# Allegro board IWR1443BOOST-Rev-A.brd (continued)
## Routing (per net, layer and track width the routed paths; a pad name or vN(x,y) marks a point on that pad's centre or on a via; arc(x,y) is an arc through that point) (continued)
AR_SPICLK1: length 44.7
  TOP w0.102: v1(37.19,33.76) 36.37,34.58 36.37,35.19 36.18,35.38 R76.1 35.04,35.38 R75.1 ; v1(60.55,53.34) 60.5,53.29 60.5,49.99 60.5,49.99 60.5,46.82 60.24,46.56 60.24,46.45 U2.R9
  L4 w0.127: v1(60.55,53.34) 56.84,53.34 55.62,52.12 54.62,52.12 49.24,46.75 47.42,46.75 41.83,41.16 40.33,41.16 36.87,37.71 36.87,34.07 v1(37.19,33.76)
AR_SYNC_IN: length 87.2
  TOP w0.102: v1(27.27,46.79) 27.27,46.3 26.64,45.67 26.64,44.91 26.47,44.74 R62.2 ; U2.N10 59.59,44.87 59.91,44.55 59.91,43.81 v1(60.2,43.53)
  L3 w0.127: v1(27.27,46.79) 28.32,47.83 29.44,47.83 29.85,47.42 34.77,47.42 37.36,44.83 46.8,44.83 48.12,46.15 54.22,46.15 54.96,45.42 59.21,45.42 59.89,44.74 59.89,43.84 v1(60.2,43.53)
  L4 w0.127: v1(25.67,21.51) 23.34,19.18 v1(23.34,15.82)
  BOTTOM w0.102: R165.1 26,8.11 25.9,8.21 25.9,9.09 25.06,9.93 25.06,14.07 23.34,15.8 v1(23.34,15.82) ; v1(27.27,46.79) 27.85,46.79 32.24,42.39 32.24,35.58 32.07,35.41 32.07,27.91 v1(25.67,21.51)
AR_SYNC_OUT_SOP1: length 95
  TOP w0.102: v1(57.91,51.18) 59.48,49.61 59.48,47.5 58.62,46.65 58.62,45.88 U2.P11 ; R113.1 18.61,14.48 29.44,14.48 29.64,14.29 31.03,14.29 31.21,14.46 33.26,14.46 35.94,17.13 R108.2 36.4,19.89 v1(36.23,20.07)
  L3 w0.127: v1(38.73,53.26) 38.73,53.35 39.63,54.25 40.13,54.25 40.58,54.71 42.07,54.71 43.01,53.77 43.89,53.77 43.98,53.86 46.27,53.86 49.32,56.91 51.56,56.91 54.75,53.71 54.75,52.77 55.13,52.39 55.64,52.39 56.69,51.35 57.74,51.35 v1(57.91,51.18)
  BOTTOM w0.102: v1(38.73,53.26) 35.06,53.26 31.78,49.98 31.78,45.08 33.93,42.93 33.93,33.76 33.32,33.15 33.32,32.13 33.88,31.57 33.88,25.17 33.38,24.67 33.38,22.85 36.16,20.07 v1(36.23,20.07)
AR_TCK: length 33.2
  TOP w0.102: R70.1 30.34,43.88 R66.2 30.57,44.74 30.7,44.86 30.7,45.87 v1(30.22,46.35) ; U2.M13 57.65,44.25 v1(58.13,44.25)
  L3 w0.127: v1(30.22,46.35) 31.03,47.17 34.67,47.17 37.26,44.58 46.91,44.58 47.13,44.81 50.87,44.81 51.56,44.12 56,44.12 56.13,44.25 v1(58.13,44.25)
AR_TDI: length 51.2
  TOP w0.102: U2.H13 58.05,41.67 v1(58.13,41.59) ; R29.1 R30.1 27.9,59.07 27.8,59.17 27.77,59.17 27.77,59.21 v1(27.76,59.21)
  L3 w0.127: v1(26.05,46.15) 26.05,45.43 27.87,43.61 35.66,43.61 38.4,40.87 51.5,40.87 52.24,41.61 56.86,41.61 56.88,41.59 v1(58.13,41.59)
  BOTTOM w0.102: v1(26.05,46.15) 25.83,46.38 25.83,50.57 26.83,51.58 26.83,56.7 26.57,56.96 26.57,58.02 v1(27.76,59.21)
AR_TDO_SOP0: length 56.6
  TOP w0.102: R89.1 27.55,24.96 v1(27.58,24.99) ; v1(59.01,42.37) 58.96,42.32 U2.J13 ; v1(30.3,42.37) 30.98,42.37 31.53,42.92 31.53,43.65 31.31,43.87 R71.1 31.17,43.87 R67.2 31.55,44.74 32.45,45.64 v1(32.45,46.28)
  L3 w0.127: v1(32.45,46.28) 33.42,46.28 38.58,41.12 51.12,41.12 52.26,42.26 58.9,42.26 v1(59.01,42.37)
  BOTTOM w0.102: v1(27.58,24.99) 30.28,27.7 30.28,33.84 29.58,34.54 29.58,41.66 v1(30.3,42.37)
AR_TMS: length 38.8
  TOP w0.102: v1(28.11,44.27) 28.19,44.27 28.59,43.87 R69.1 R65.2 ; U2.L13 58.82,43.62 v1(58.9,43.54)
  L3 w0.127: v1(28.11,44.27) 29.55,44.27 32.19,46.92 33.27,46.92 38.81,41.38 50.84,41.38 52.2,42.74 56.97,42.74 57.78,43.54 v1(58.9,43.54)
AR_VBGAP: length 2.3
  TOP w0.381: U2.B10 59.59,37.84 v1(59.13,38.3)
  BOTTOM w0.508: v1(59.13,38.3) 58.32,37.49 C56.2
AR_VOUT_PA:
  vias: v1(66.72,33.74) v1(66.82,34.53)
AR_VSENSE: length 62.2
  TOP w0.102: v1(56.99,39.07) U2.C14
  L3 w0.127: P1.1 5.33,47.29 5.33,42.71 7.98,40.06 51.68,40.06 52.7,41.07 55.46,41.07 56.52,40.01 56.52,39.54 v1(56.99,39.07)
AR_WARMRST: length 40.6
  TOP w0.102: v1(55.24,49.12) 55.14,49.12 55.04,49.02 55.04,48.01 56.66,46.38 56.66,46.1 56.87,45.88 57.12,45.88 57.32,45.69 57.32,45.44 57.52,45.24 57.97,45.24 U2.N12 ; R18.1 28.73,58.6 29.67,59.54 30.65,59.54 30.91,59.28 R15.1 31.14,58.67 31.18,58.67 31.21,58.65 31.21,58.6 31.69,58.12 v1(31.69,58.01)
  L3 w0.127: v1(55.24,49.12) 54.48,49.89 54.48,51.58 52.85,53.2 47.39,53.2 46.32,52.13 43.53,52.13 42.56,53.1 41.24,53.1 41.04,52.9 39.26,52.9 38.99,52.63 38.45,52.63 38.09,52.98 35.52,52.98 32.73,55.77 32.73,56.97 v1(31.69,58.01)
AR_XTALM: length 7.8
  TOP w0.102: C9.2 51.42,38.27 Y1.1 51.94,37.98 52.83,38.86 54.91,38.86 56.19,40.15 56.77,40.15 U2.F14
AR_XTALP: length 7.4
  TOP w0.102: U2.E14 56.83,39.72 56.5,39.39 56.09,39.39 55.11,38.4 55.11,37.08 53.79,35.77 Y1.3 54.06,35.33 C15.2
CAN1_RX: length 39.4
  TOP w0.102: v1(31.79,36.22) 29.94,36.22 28.44,34.72 28.44,32.74 29.08,32.11 U3.4 ; R12.2 25.27,62 v1(25.15,62.12)
  BOTTOM w0.102: v1(31.79,36.22) 31.79,42.51 28.26,46.04 27.29,46.04 26.95,45.7 25.77,45.7 24.68,46.79 24.68,55.93 24.28,56.33 24.28,59.29 25.15,60.16 v1(25.15,62.12)
CAN1_TX: length 37.4
  TOP w0.102: R11.2 30.33,61.94 30.3,61.98 v1(30.3,62.1) ; v1(32.61,30.35) 32.89,30.63 U3.1
  BOTTOM w0.102: v1(32.61,30.35) 32.35,30.61 32.35,33.6 33.01,34.26 33.01,42.49 28.17,47.33 28.17,52.13 30.33,54.28 30.33,58.66 30.57,58.9 30.57,59.31 30.3,59.58 v1(30.3,62.1)
LDO_01_EN: length 2.7
  TOP w0.305: U4.5 52.06,25.77
  TOP w0.508: R83.1 R84.2 52.06,25.77
LDO_02_EN: length 9.7
  TOP w0.102: R46.2 40.36,46.26 R47.1 42.38,46.26 v1(42.49,46.15)
  L3 w0.127: v1(42.49,46.15) 42.49,50.43 v1(42.97,50.91)
  BOTTOM w0.102: v1(42.97,50.91) 43.02,50.91 43.64,50.3 U5.6 ; v1(42.49,46.15) 42.71,45.93 U5.20
MCU_3V3: length 78.3
  TOP w0.889: v1(20.72,13.84) 21.05,13.51 31.48,13.51 31.81,13.84 33.8,13.84 v1(34.94,14.99) ; v1(41.57,53.82) 40.3,52.55 39.21,52.55 37.1,50.44 37.1,47.76 38.98,45.89 v1(38.98,45.72)
  L4 w0.889: v1(34.94,14.99) 34.94,14.99 35.1,15.14 35.1,21.87 35.48,22.25 35.48,30.26 35.25,30.49 35.25,33.2 34.64,33.81 34.64,41.39 v1(38.98,45.72)
  BOTTOM w0.889: v1(41.57,53.82) 41.57,55.75 42.46,56.64 43.22,56.64 47.34,60.76 J4.3 ; R130.1 v1(38.98,45.72)
  BOTTOM w1.016: J6.1 16.01,13.12 16.73,13.84 v1(20.72,13.84)
MCU_5V: length 2.9
  BOTTOM w1.016: v1(15.08,18.53) 15.08,18.48 16.01,17.55 J6.2 16.7,16.66 v1(17.04,16.66)
  vias: v1(13.84,18.5) v1(16.94,18.58) v1(47.95,14.61) v1(48.05,15.54) v1(48.2,13.72) v1(49.4,13.67)
MCU_SOP0: length 42.7
  TOP w0.102: v1(37.87,53.8) 38.07,54.01 R36.1 ; R93.2 27.54,20.96 28.82,20.96 v1(29.08,21.21)
  BOTTOM w0.102: v1(29.08,21.21) 33.6,25.73 33.6,31.45 33.07,31.97 33.07,33.23 33.69,33.85 33.69,42.83 31.55,44.98 31.55,50.08 35.01,53.54 37.61,53.54 v1(37.87,53.8)
MCU_SOP1: length 51.4
  TOP w0.102: R112.2 19.56,15.02 19.68,15.14 19.68,16.59 21.98,18.9 25.47,18.9 v1(26.61,20.04) ; v1(35.4,54) 35.43,54 35.43,54.01 R35.1
  BOTTOM w0.102: v1(26.61,20.04) 26.61,21.26 33.32,27.97 33.32,31.32 32.84,31.79 32.84,33.33 33.46,33.95 33.46,42.73 31.32,44.87 31.32,50.38 34.94,54 v1(35.4,54)
MCU_SOP2: length 64.6
  TOP w0.102: v1(25.65,20.29) 25.51,20.16 21.09,20.16 18.85,22.4 11.96,22.4 11.6,22.05 11.6,17.86 R101.2 ; R32.1 v1(34.26,58.55)
  BOTTOM w0.102: v1(25.65,20.29) 25.65,20.68 33.09,28.12 33.09,31.14 32.61,31.62 32.61,33.43 33.23,34.05 33.23,42.6 31.09,44.75 31.09,50.66 32.94,52.5 32.94,57.23 v1(34.26,58.55)
PGOOD: length 115.6
  TOP w0.381: R27.1 24.62,58.91 24.25,59.28
  TOP w0.508: 24.25,59.28 23.54,59.28 v1(23.21,58.95) ; R107.2 32.07,17.29 32.13,17.23 v1(32.2,17.23) 32.28,17.23 32.79,17.74 32.79,18.88 35.35,21.45 35.35,28.35 37.33,30.34 37.33,32.59 v1(36.19,33.73)
  L3 w0.508: v1(23.21,58.95) 26.27,58.95 28.54,61.23 37.69,61.23 38.35,61.89 43.1,61.89 45.26,59.73 v1(45.26,57.35) ; v1(2.03,18.97) 4.2,18.97 4.47,18.71 10.45,18.71 11.56,19.82 19.42,19.82 20.21,19.04 24.87,19.04 25.92,18 31.36,18 32.13,17.23 v1(32.2,17.23)
  L4 w0.508: v1(45.26,57.35) 46.85,55.76 46.85,52.02 48.47,50.39 48.47,48.44 41.65,41.62 39.57,41.62 35.5,37.55 35.5,34.42 v1(36.19,33.73)
  BOTTOM w0.508: R159.1 2.37,18.63 v1(2.03,18.97) ; v1(36.19,33.73) 35.89,34.03 R138.2 35.97,34.46 R141.2
PMIC_1V2: length 26.1
  TOP w0.254: U2.P14 U2.P15 55.88,45.57 55.21,46.23 ; 56.15,47.47 56.99,46.64 U2.R14
  TOP w0.305: 62.03,47.46 62.02,47.45 62.02,46.89 62.19,46.72 U2.R6
  TOP w0.381: U2.F13 58.08,40.37 v1(58.13,40.42) ; v1(59.25,44.48) 59.25,44.5 58.94,44.81 U2.N11
  TOP w0.508: v1(53.64,47.75) 53.65,47.75 53.65,47.78 ; 53.65,47.78 53.52,47.65 C7.2 ; 53.65,47.78 C6.2 54.49,46.95 55.21,46.23 ; 56.15,47.47 56.15,48.01 C4.2 55.7,47.98 v1(55.54,48.13) ; v1(62.6,49.86) 62.61,49.86 C3.2 62.03,48.53 62.03,47.46
  BOTTOM w0.254: L1.2 46.99,40.11 48.54,38.56 48.54,35.1 48.36,34.92 47.43,34.92 45.9,33.39 U8.14
  vias: v1(45.92,42.54) v1(47.21,42.57) v1(48.33,42.93)
PMIC_1V8: length 7
  BOTTOM w0.254: U8.1 38.72,29.75 38.35,29.38 36.68,29.38 36.39,29.08
  BOTTOM w0.508: 41.78,49.25 41.78,50.83 R120.2
  vias: v1(39.54,47.74) v1(39.54,46.85) v1(40.25,47.92)
PMIC_2V3: length 17.3
  TOP w0.508: 47.72,23.29 47.72,23.98 49.49,25.75 R84.1
  BOTTOM w0.254: 45.85,22.54 46.81,22.54 48.15,23.89 48.15,28.46 47.87,28.74 47.14,28.74 46.25,29.63 45.28,29.63 45.16,29.75 U8.21
  vias: v1(47.21,20.62) v1(47.52,21.54) v1(48.28,20.7) v1(48.71,21.64) v1(56.74,26.23) v1(57.52,26.35) v1(58.29,26.35)
PMIC_CLK: length 44.5
  TOP w0.18: v1(38.12,29.93) 38.04,29.86 37.89,29.86 36.01,27.98 36.01,21.32 v1(36.26,21.07)
  TOP w0.279: R97.2 10.1,17.79 v1(10.1,19.53)
  L3 w0.229: v1(10.1,19.53) 10.1,19.74 12.57,22.21 19.66,22.21 21.82,20.05 24.79,20.05 26.21,18.63 29.76,18.63 32.2,21.07 v1(36.26,21.07)
  BOTTOM w0.229: U8.3 39.54,30.82 39.41,30.95 38.94,30.95 38.58,30.59 38.58,30.39 v1(38.12,29.93)
PMIC_EN: length 34.8
  TOP w0.102: v1(50.54,32.92) 50.54,33.67 49.04,35.17 48.53,35.17 48.18,34.81 48.18,33.97 47.62,33.41 40.11,33.41 v1(39.38,32.68) 39,33.06 38.14,33.06 37.76,32.67 37.76,30.18 35.75,28.18 35.75,21.27 33.86,19.37 R102.2
  BOTTOM w0.102: R142.1 50.54,33.65 v1(50.54,32.92) ; U8.7 39.52,32.82 v1(39.38,32.68)
PMIC_NRST: length 5.8
  BOTTOM w0.102: U8.20 45.08,30.32 45.47,29.93 46.44,29.93 46.62,29.76 47.9,29.76 48.35,29.3 48.99,29.3 R150.2
PMICOUT_3V3: length 10.3
  BOTTOM w0.254: U8.8 38.42,33.39 37.46,34.35 37.46,34.99 37.03,35.42 R141.1
  BOTTOM w0.508: 38.1,40.08 37.38,40.08 36.9,39.59 R141.1
PMICVIO_3V3: length 9.6
  BOTTOM w0.102: 48.53,33.76 R143.2
  BOTTOM w0.508: R150.1 49.19,31.08 R145.2 49.36,31.08 49.4,31.12 49.52,31.12 49.93,31.52 49.93,32.45 49.46,32.92 R142.2 ; R150.1 48.31,30.06 R147.2 ; R150.1 50.23,30.06 R148.2 51.27,30.07 R149.1 ; R142.2 48.53,33.76 ; R142.2 R139.2
RX1: length 5.6
  TOP w0.18: U2.M2 66.02,44.27 arc(66.89,44.44) 67.63,44.94 arc(67.88,45.11) 68.17,45.16 70.1,45.16
RX2: length 5.6
  TOP w0.18: U2.K2 66.42,42.97 arc(66.76,43.03) 67.04,43.22 arc(67.44,43.49) 67.92,43.59 69.05,43.59 arc(69.29,43.54) 69.49,43.4 69.49,43.4 arc(69.65,43.3) 69.83,43.26 70.1,43.26
RX3: length 5.6
  TOP w0.18: U2.H2 66.42,41.67 arc(66.76,41.6) 67.04,41.41 arc(67.44,41.14) 67.92,41.05 69.05,41.05 arc(69.29,41.09) 69.49,41.23 69.49,41.23 arc(69.65,41.33) 69.83,41.37 70.1,41.37
RX4: length 5.6
  TOP w0.18: U2.F2 66.02,40.37 arc(66.89,40.19) 67.63,39.69 67.63,39.69 arc(67.88,39.52) 68.18,39.46 70.11,39.46
SS_CTRL: length 25.7
  L4 w0.127: v1(41.6,43.69) 41.6,46.42 41.07,46.95 41.07,49.97 43.78,52.69 43.78,54.05 v1(43.43,54.41)
  BOTTOM w0.102: U5.18 44.64,45.3 44.06,44.73 44.06,43.55 43.66,43.14 42.14,43.14 v1(41.6,43.69) ; U5.8 44.64,52.59 44.74,52.69 44.75,52.69 45.03,52.97 45.03,53.66 44.28,54.41 v1(43.43,54.41) 43.43,54.41 42.87,53.85 42.87,53.84 42.84,53.81 42.84,53.78 42.8,53.78 R119.2 R120.1
SW0: length 8.4
  BOTTOM w0.254: 41.03,35.04 41.51,34.56 U8.10
  BOTTOM w0.432: 39.44,38.1 40.22,37.31 40.22,35.57 40.75,35.04 41.03,35.04
  BOTTOM w0.508: R190.2 37.92,37.66 L2.2
  BOTTOM w0.635: L2.2 39.44,38.1
SW1: length 9.1
  BOTTOM w0.254: U8.12 42.51,34.59 43.02,35.1
  BOTTOM w0.432: 44.59,38.11 43.81,37.33 43.81,35.51 43.4,35.1 43.02,35.1
  BOTTOM w0.508: R191.2 46.67,37.56 46.12,38.11 L1.1
  BOTTOM w0.635: L1.1 44.59,38.11
SW2: length 9.6
  BOTTOM w0.254: 41.26,27.77 41.51,28.02 U8.25
  BOTTOM w0.432: 41.26,27.77 41.05,27.56 40.66,27.56 40.2,27.1 40.2,25.34 39.34,24.48
  BOTTOM w0.508: R192.2 37.28,24.99 37.79,24.48 L4.2
  BOTTOM w0.635: 39.34,24.48 L4.2
SW3: length 9.6
  BOTTOM w0.254: U8.23 42.51,28.11 42.96,27.66
  BOTTOM w0.432: 42.96,27.66 43.32,27.66 43.72,27.26 43.72,25.33 44.54,24.51 44.59,24.51
  BOTTOM w0.508: L3.1 46.17,24.48 46.69,25 R193.2
  BOTTOM w0.635: L3.1 44.62,24.48 44.59,24.51
TX1: length 17.7
  TOP w0.18: U2.B4 63.49,32.12 arc(64.15,30.53) 65.74,29.87 67.8,29.87 arc(68.45,30) 68.99,30.36 arc(69.33,30.87) 69.45,31.46 arc(69.35,31.98) 69.06,32.41 arc(68.81,32.77) 68.73,33.2 arc(68.81,33.6) 69.03,33.93 arc(69.35,34.15) 69.73,34.22 70.11,34.22
TX2: length 17.7
  TOP w0.18: 72.01,30.42 70.99,30.42 arc(70.71,30.37) 70.48,30.21 70.48,30.21 arc(68.78,29.08) 66.78,28.68 arc(64.66,29.1) 62.86,30.31 62.86,30.31 arc(62.37,31.05) 62.19,31.92 U2.B6
TX3: length 17.7
  TOP w0.18: U2.B8 60.89,37.76 60.89,31.79 arc(61.16,30.39) 61.95,29.21 arc(64.82,27.3) 68.2,26.62 70.11,26.62
UNNAMED_2_AR1243PRELIMINARY_I28: length 65.5
  TOP w0.102: TP2.1 7.63,48.3 C8.2 8.17,45.92 v1(8.17,45.54)
  TOP w0.254: v1(59.01,41.02) 58.55,41.02 58.55,41.02 U2.G13
  L3 w0.127: v1(59.01,41.02) 59.01,40.4 58.39,39.78 57.7,39.78 56.15,41.33 52.52,41.33 51.53,40.34 8.06,40.34 5.58,42.81 5.58,44.54 6.59,45.54 v1(8.17,45.54)
UNNAMED_4_CAPNONPOLARIZED_I52_2: length 2.4
  TOP w0.305: U4.6 54.31,24.67
  TOP w0.381: 54.31,24.67 53.84,24.21 53.16,24.21 C22.2
UNNAMED_4_CAPNONPOLARIZED_I53_1: length 4.2
  TOP w0.305: U4.3 54.31,30.24 C18.1
  TOP w0.381: C18.1 54.13,30.63 54.59,31.09 R82.1 54.59,31.69 R81.2
UNNAMED_6_1280711201_I42_S: length 2.3
  TOP w0.18: J2.S 57.44,13.12 R111.2
UNNAMED_6_QSH03001XD_I1_4: length 4.3
  TOP w0.102: J1.4 30.04,47.88 31.24,46.69 31.24,45.46 R67.1
UNNAMED_6_QSH03001XD_I1_5: length 6.1
  TOP w0.102: R29.2 27.04,57.85 27.04,57.25 27.02,57.25 v1(27.02,57.23) ; J1.5 29.54,56.26 v1(29.86,56.59)
  BOTTOM w0.102: v1(29.86,56.59) 28.7,57.76 27.55,57.76 v1(27.02,57.23)
UNNAMED_6_QSH03001XD_I1_6: length 4.2
  TOP w0.102: J1.6 29.54,48 29.84,47.7 29.84,46.91 29.78,46.86 29.78,46 30.34,45.45 R66.1
UNNAMED_6_QSH03001XD_I1_7: length 3.2
  TOP w0.102: J1.7 29.04,56.14 29.25,56.36 29.25,57.63 R17.2
UNNAMED_6_QSH03001XD_I1_8: length 4.1
  TOP w0.102: R65.1 29.51,45.4 29.51,46.89 29.62,47 29.62,47.47 29.04,48.05 J1.8
UNNAMED_6_QSH03001XD_I1_9: length 25.4
  TOP w0.102: R75.2 32.75,34.73 v1(32.56,34.92) ; J1.9 28.54,53.51 v1(27.91,52.88)
  BOTTOM w0.102: v1(32.56,34.92) 32.56,42.47 27.07,47.96 27.07,50.85 27.91,51.69 v1(27.91,52.88)
UNNAMED_6_QSH03001XD_I1_10: length 4
  TOP w0.102: J1.10 28.54,47.69 28.39,47.55 28.39,45.69 R64.1
UNNAMED_6_QSH03001XD_I1_11: length 4.6
  TOP w0.102: J1.11 28.04,56.23 27.49,56.78 26.56,56.78 R28.2
UNNAMED_6_QSH03001XD_I1_12: length 15.9
  TOP w0.102: J1.12 28.04,50.34 v1(28.62,50.93) ; v1(32.28,62.08) 32.11,61.91 R7.1
  BOTTOM w0.102: v1(28.62,50.93) 29.15,50.93 32.14,53.92 32.14,58.84 31.93,59.05 31.93,61.73 v1(32.28,62.08)
UNNAMED_6_QSH03001XD_I1_13: length 4.9
  TOP w0.254: 27.04,56.4 27.27,56.4 27.54,56.14 J1.13
  TOP w0.381: 27.04,56.4 26.08,56.4 24.62,57.86 R27.2
UNNAMED_6_QSH03001XD_I1_14: length 4.5
  TOP w0.102: R63.1 28.19,46.54 28.19,47.37 27.54,48.02 J1.14
UNNAMED_6_QSH03001XD_I1_16: length 4.1
  TOP w0.102: J1.16 27.04,49.16 27.04,47.5 26.71,47.17 26.71,46.05 26.23,45.56 R62.1
UNNAMED_6_QSH03001XD_I1_20: length 4.5
  TOP w0.132: J1.20 26.04,47.87 25.92,47.75 25.92,46.98 25.63,46.7 25.28,46.7 25.14,46.57 25.14,45.66 R61.1
UNNAMED_6_QSH03001XD_I1_22: length 4.5
  TOP w0.132: R60.1 24.89,45.69 24.89,46.67 25.17,46.96 25.52,46.96 25.66,47.09 25.66,47.75 25.54,47.87 J1.22
UNNAMED_6_QSH03001XD_I1_26: length 4.3
  TOP w0.132: R59.1 23.49,45.68 23.49,46.35 24.42,47.28 24.42,47.75 24.54,47.87 J1.26
UNNAMED_6_QSH03001XD_I1_28: length 4.3
  TOP w0.132: J1.28 24.04,47.87 24.16,47.75 24.16,47.39 23.23,46.46 23.23,45.68 R58.1
UNNAMED_6_QSH03001XD_I1_32: length 4.7
  TOP w0.132: R57.1 21.84,45.68 21.84,45.91 21.97,46.05 22.43,46.05 22.92,46.53 22.92,47.75 23.04,47.87 J1.32
UNNAMED_6_QSH03001XD_I1_34: length 4.7
  TOP w0.132: R56.1 21.58,45.68 21.58,46.02 21.86,46.3 22.32,46.3 22.66,46.64 22.66,47.75 22.54,47.87 J1.34
UNNAMED_6_QSH03001XD_I1_38: length 4.4
  TOP w0.132: R55.1 20.22,45.67 20.22,45.89 20.65,46.32 20.65,46.74 21.42,47.51 21.42,47.75 21.54,47.87 J1.38
UNNAMED_6_QSH03001XD_I1_40: length 4.4
  TOP w0.132: R54.1 19.96,45.69 19.96,46 20.39,46.43 20.39,46.85 21.16,47.62 21.16,47.75 21.04,47.87 J1.40
UNNAMED_6_QSH03001XD_I1_44: length 4.5
  TOP w0.132: J1.44 20.04,47.93 19.9,47.79 19.9,47.5 18.54,46.14 18.54,45.68 R53.1
UNNAMED_6_QSH03001XD_I1_46: length 4.5
  TOP w0.132: R52.1 18.28,45.68 18.28,46.25 19.64,47.61 19.64,47.79 19.54,47.89 J1.46
UNNAMED_6_QSH03001XD_I1_50: length 4.6
  TOP w0.132: R51.1 16.89,45.68 16.89,45.82 18.41,47.35 18.41,47.83 18.54,47.96 J1.50
UNNAMED_6_QSH03001XD_I1_51: length 3.2
  TOP w0.102: J1.51 18.03,54.92 18.03,56.36 17.52,56.87 17.52,57.37 17.41,57.49 R23.2
UNNAMED_6_QSH03001XD_I1_52: length 4.6
  TOP w0.132: J1.52 18.04,47.92 18.15,47.81 18.15,47.45 16.63,45.93 16.63,45.68 R50.1
UNNAMED_6_QSH03001XD_I1_53: length 3.6
  TOP w0.102: R22.2 16.58,56.84 17.06,56.36 17.44,56.36 17.54,56.26 J1.53
UNNAMED_6_QSH03001XD_I1_55: length 3.5
  TOP w0.102: J1.55 17.04,56.06 16.38,56.72 16.38,57.26 R33.2
UNNAMED_6_QSH03001XD_I1_56: length 4.6
  TOP w0.132: R49.1 15.23,45.68 15.23,45.85 16.92,47.53 16.92,47.76 17.04,47.88 J1.56
UNNAMED_6_QSH03001XD_I1_57: length 4.1
  TOP w0.102: J1.57 16.54,56.27 16.02,56.79 15.26,56.79 14.91,57.13 R21.2
UNNAMED_6_QSH03001XD_I1_58: length 4.6
  TOP w0.132: J1.58 16.54,47.87 16.66,47.75 16.66,47.64 14.98,45.96 14.98,45.68 R48.1
UNNAMED_6_QSH03001XD_I1_59: length 4.2
  TOP w0.102: R20.2 14.68,57.3 14.68,57.07 15.19,56.57 15.84,56.57 16.04,56.37 J1.59
UNNAMED_9_BSS123_I134_D: length 4.5
  TOP w0.508: Q1.3 4.31,18.65 4.31,19.53 3.38,20.47 DS3.C
UNNAMED_9_BSS123_I134_G: length 1.6
  TOP w0.508: R116.2 4.44,14.7 Q1.1
UNNAMED_9_BSS123_I147_D: length 4.7
  TOP w0.508: v1(6.06,16.23) 6.8,16.23 7.83,15.2 DS4.C
  BOTTOM w0.508: Q2.3 5.67,16.62 v1(6.06,16.23)
UNNAMED_9_BSS123_I147_G: length 5
  BOTTOM w0.508: Q2.1 6.62,14.76 5.44,13.57 3.64,13.57 3.29,13.93 R160.2
UNNAMED_9_DIODESCHOTTKY_I159_C: length 1.4
  TOP w0.381: 2.84,33.84 D1.C
  TOP w0.508: R77.2 2.84,33.84
UNNAMED_9_DIODESCHOTTKY_I160_C: length 1.4
  TOP w0.381: 2.87,32.22 D2.C
  TOP w0.508: R80.2 2.87,32.22
UNNAMED_9_KMR2XXG_I138_2: length 2.1
  TOP w0.381: SW2.2 9.21,33.92 9.21,32.2 R79.2
UNNAMED_9_KMR2XXG_I141_2: length 2.6
  TOP w0.381: R72.1 7.5,39.95 R73.2
  TOP w0.508: R73.2 7.54,39.88 7.84,39.88 7.88,39.84 SW1.2
UNNAMED_9_KMR2XXG_I141_4: length 1.8
  TOP w0.381: SW1.4 9.11,42.85 R68.1
UNNAMED_9_LEDS_I102_A: length 1.4
  TOP w0.508: R100.1 8.56,17.76 DS2.A
UNNAMED_9_LEDS_I105_A: length 4.9
  TOP w0.508: R90.1 7.13,21.82 7.13,19.48 6.52,18.88 DS1.A
UNNAMED_9_LEDS_I135_A: length 2.1
  TOP w0.508: R103.1 3.28,17.9 3.04,18.13 DS3.A
UNNAMED_9_LEDS_I146_A: length 1.3
  TOP w0.508: DS4.A 10.44,13.6 R117.1
UNNAMED_10_RESISTOR_I30_2: length 3.5
  TOP w0.102: R98.2 10.93,17.54 11.89,16.57 R101.1 11.94,16.58 R99.1 13.01,15.61 R114.2
UNNAMED_10_RESISTOR_I33_2: length 3.8
  TOP w0.102: P3.1 12.69,20.83 12.69,17.86 R99.2
UNNAMED_10_RESISTOR_I35_1: length 3
  TOP w0.102: R113.2 18.07,15.98 R96.2 19.08,16.96 R95.1 19.09,15.99 R112.1
UNNAMED_10_RESISTOR_I36_2: length 3.6
  TOP w0.102: R95.2 19.09,20.22 P2.1
UNNAMED_10_RESISTOR_I39_1: length 3.1
  TOP w0.102: R88.2 26.51,22.92 R92.1 R93.1 27.53,22.9 R89.2
UNNAMED_10_RESISTOR_I39_2: length 3.2
  TOP w0.102: R92.2 23.56,20.95 P4.1
UNNAMED_15_RESISTOR_I43_1: length 2.2
  TOP w0.102: R102.1 33.86,15.89 v1(33.79,15.82)
  BOTTOM w0.102: J6.16 v1(33.79,15.82)
UNNAMED_15_RESISTOR_I44_2: length 3.9
  BOTTOM w0.102: R169.2 R168.2 21.09,8.96 J6.5
UNNAMED_15_RESISTOR_I45_2: length 3.8
  BOTTOM w0.102: R166.2 23.73,8.76 ; 23.73,8.76 R167.2 ; 23.73,8.76 23.63,8.86 J6.7
UNNAMED_15_RESISTOR_I46_2: length 3
  BOTTOM w0.102: R165.2 26.17,8.9 J6.9
UNNAMED_15_RESISTOR_I47_2: length 25.6
  TOP w0.102: v1(34.06,32.77) 34.21,32.77 35.88,34.44 R76.2
  L4 w0.127: v1(34.06,32.77) 34.61,32.21 34.61,22.83 34.42,22.65 34.42,15.37 32.18,13.12 v1(32.18,13)
  BOTTOM w0.102: J6.13 31.25,12.33 31.92,13 v1(32.18,13)
UNNAMED_15_RESISTOR_I48_2: length 4.8
  BOTTOM w0.102: R164.2 36.57,9.22 36.57,9.86 36.24,10.2 35.29,10.2 J6.15
UNNAMED_15_RESISTOR_I49_2: length 3.5
  BOTTOM w0.102: J6.17 36.33,11.35 37.92,9.76 R163.2
UNNAMED_15_RESISTOR_I50_2: length 3.3
  BOTTOM w0.102: R162.2 38.87,9.92 J6.19
UNNAMED_15_RESISTOR_I51_2: length 4.7
  TOP w0.102: v1(13.43,57.05) 13.26,57.22 R19.2
  BOTTOM w0.102: J5.1 16.01,55.46 14.42,57.05 v1(13.43,57.05)
UNNAMED_15_RESISTOR_I52_2: length 3.6
  TOP w0.102: R24.2 19.88,57.35 v1(19.6,57.07)
  BOTTOM w0.102: v1(19.6,57.07) 18.55,56.02 J5.3
UNNAMED_15_RESISTOR_I53_2: length 3
  TOP w0.102: v1(21.09,56.98) 21.09,57.86 R25.2
  BOTTOM w0.102: J5.5 v1(21.09,56.98)
UNNAMED_15_RESISTOR_I54_2: length 4.4
  TOP w0.102: R26.2 23.79,57.89 23.79,57.25 24.52,56.52 24.67,56.52 v1(24.73,56.59)
  BOTTOM w0.102: v1(24.73,56.59) 25.09,56.59 26.17,55.51 J5.9
UNNAMED_15_RESISTOR_I55_2: length 3.6
  TOP w0.102: v1(31.67,56.59) 31.59,56.59 31.59,56.67 32.5,57.58 R31.2
  BOTTOM w0.102: v1(31.67,56.59) 31.67,55.96 31.25,55.54 J5.13
UNNAMED_15_RESISTOR_I56_2: length 3.1
  TOP w0.102: v1(28.8,56.54) 28.8,57.83 R18.2
  BOTTOM w0.102: J5.11 28.8,54.97 v1(28.8,56.54)
UNNAMED_15_RESISTOR_I57_2: length 2.2
  TOP w0.102: v1(37.26,54.61) 36.98,54.89 36.53,54.89 R35.2
  BOTTOM w0.102: J5.17 36.98,54.88 v1(37.26,54.61)
UNNAMED_15_RESISTOR_I58_2: length 2.1
  TOP w0.102: R36.2 39.31,55.12 39.72,55.12 v1(39.8,55.04)
  BOTTOM w0.102: v1(39.8,55.04) 39.64,54.88 J5.19
UNNAMED_15_RESISTOR_I59_2: length 3.5
  TOP w0.102: v1(34.49,56.92) 35.07,57.51 35.07,57.88 R32.2
  BOTTOM w0.102: v1(34.49,56.92) 34.49,56.21 33.79,55.51 J5.15
UNNAMED_15_RESISTOR_I60_1: length 2.6
  TOP w0.102: v1(22.7,61.39) 22.75,61.39 22.75,61.4 R9.1
  BOTTOM w0.102: v1(22.7,61.39) 22.7,60.78 22.95,60.53 J5.8
UNNAMED_15_RESISTOR_I61_1: length 2.7
  TOP w0.102: v1(26.17,62.29) 26.17,61.49 R2.1
  BOTTOM w0.102: J5.10 v1(26.17,62.29)
UNNAMED_15_RESISTOR_I62_1: length 2.7
  TOP w0.102: R1.1 v1(21.15,62.3)
  BOTTOM w0.102: v1(21.15,62.3) 21.09,62.24 J5.6
UNNAMED_15_RESISTOR_I63_1: length 7.2
  TOP w0.102: R3.1 27.74,62.19 28.43,62.88 30.49,62.88 v1(31.29,62.08) 31.26,62.05 R6.1
  BOTTOM w0.102: J5.14 31.25,62.04 v1(31.29,62.08)
UNNAMED_15_RESISTOR_I64_1: length 2.7
  TOP w0.102: R10.1 34.09,61.63 v1(34.53,62.06)
  BOTTOM w0.102: J5.16 33.79,61.33 v1(34.53,62.06)
UNNAMED_15_RESISTOR_I65_1: length 3.2
  TOP w0.102: R5.1 R4.1 28.58,61.96 v1(28.76,62.14)
  BOTTOM w0.102: v1(28.76,62.14) 28.71,62.09 J5.12
UNNAMED_15_RESISTOR_I66_1: length 2.3
  TOP w0.102: R8.1 v1(36.38,62.11)
  BOTTOM w0.102: v1(36.38,62.11) 36.33,62.06 J5.18
UNNAMED_15_RESISTOR_I67_1: length 2.7
  TOP w0.102: R104.1 20.36,16.48 20.36,16.46 v1(20.16,16.46)
  BOTTOM w0.102: J6.6 21.09,16.62 20.92,16.46 v1(20.16,16.46)
UNNAMED_15_RESISTOR_I68_1: length 2
  TOP w0.102: v1(24.56,17.12) 24.36,17.32 R94.1
  BOTTOM w0.102: v1(24.56,17.12) 24.32,17.35 J6.8
UNNAMED_15_RESISTOR_I69_1: length 2.7
  TOP w0.102: R105.1 26.78,15.92 26.78,15.88 26.82,15.88 v1(26.82,15.85)
  BOTTOM w0.102: J6.10 26.17,16.78 26.82,16.13 v1(26.82,15.85)
UNNAMED_15_RESISTOR_I70_1: length 2.3
  TOP w0.102: R106.1 28.78,15.82 v1(28.77,15.81)
  BOTTOM w0.102: J6.12 28.71,16.5 28.8,16.41 28.8,15.84 v1(28.77,15.81)
UNNAMED_15_RESISTOR_I97_1: length 2.7
  TOP w0.102: v1(36.33,15.58) 36.4,15.66 R108.1
  BOTTOM w0.102: J6.18 v1(36.33,15.58)
UNNAMED_15_RESISTOR_I98_1: length 3.3
  TOP w0.102: R109.1 37.23,15.86 37.33,15.76 v1(37.36,15.76)
  BOTTOM w0.102: J6.20 38.87,16.76 37.87,15.76 v1(37.36,15.76)
UNNAMED_15_RESISTOR_I103_1: length 2.5
  TOP w0.508: R107.1 31.31,15.73 v1(31.18,15.61)
  BOTTOM w0.508: v1(31.18,15.61) 31.25,15.67 J6.14
UNNAMED_17_CAPNONPOLARIZED_I130: length 3.5
  BOTTOM w0.279: U5.10 45.64,50.66
  BOTTOM w0.305: 45.64,50.66 R122.1
  BOTTOM w0.508: C28.1 46.14,51.2 R122.1 45.17,51.18 R121.2
UNNAMED_17_CAPNONPOLARIZED_I131: length 1.9
  BOTTOM w0.254: U5.7 44.14,51.1 C29.2
UNNAMED_17_CAPNONPOLARIZED_I132: length 1.6
  BOTTOM w0.254: U5.19 44.14,45.29 43.56,44.71 C44.2
UNNAMED_17_CAPNONPOLARIZED_I133: length 3.7
  BOTTOM w0.254: 44.98,44.69 R132.2 44.99,44.7 45.45,45.16 45.46,45.16 45.64,45.34 U5.16 ; 46.04,43.68 C46.1
  BOTTOM w0.508: 46.04,43.68 R131.1 44.98,44.69
UNNAMED_22_CAPNONPOLARIZED_I63_: length 4.2
  TOP w0.381: U1.8 53.1,56.34 53.66,56.9 53.74,56.9
  TOP w0.508: C2.2 53.74,54.84 R37.1 53.74,56.9 C1.2
UNNAMED_22_RESISTOR_I116_2: length 1.4
  TOP w0.102: U1.3 45.25,53.8 R42.2
UNNAMED_22_RESISTOR_I117_1: length 3.5
  TOP w0.102: R44.1 53.23,51.64 53.23,53.51 52.94,53.8 U1.6
UNNAMED_22_RESISTOR_I118_1: length 3.1
  TOP w0.102: R45.1 52.33,51.39 U1.5
UNNAMED_22_RESISTOR_I119_2: length 1.5
  TOP w0.102: U1.2 45.56,55.07 R39.2
UNNAMED_22_RESISTOR_I120_1: length 3.6
  TOP w0.102: R40.1 53.66,53.87 52.45,55.07 U1.7
UNNAMED_25_CAPNONPOLARIZED_I216: length 1.6
  TOP w0.559: C86.2 37.92,35.96 v1(37.92,35.39)
  BOTTOM w0.508: R190.1 v1(37.92,35.39)
UNNAMED_25_CAPNONPOLARIZED_I217: length 1.5
  TOP w0.559: v1(46.81,35.19) 46.68,35.32 C87.2
  BOTTOM w0.559: v1(46.81,35.19) 46.67,35.32 R191.1
UNNAMED_25_CAPNONPOLARIZED_I218: length 1.6
  TOP w0.559: C88.2 37.27,27.4 v1(37.23,27.44)
  BOTTOM w0.559: R192.1 37.28,27.4 v1(37.23,27.44)
UNNAMED_25_CAPNONPOLARIZED_I219: length 1.5
  TOP w0.559: v1(46.83,27.29) 46.69,27.16 C89.2
  BOTTOM w0.559: v1(46.83,27.29) 46.69,27.16 R193.1
UNNAMED_25_P87524BRNFRQ1ES22P_1: length 13
  TOP w0.102: v1(48.41,32.12) 47.36,33.16 41.17,33.16 40.2,32.19 40.2,31.25 39.35,30.4 v1(39.22,30.4)
  BOTTOM w0.102: v1(48.41,32.12) 48.48,32.04 R145.1 ; U8.2 39.31,30.32 v1(39.22,30.4)
UNNAMED_25_P87524BRNFRQ1ES22P_2: length 3.5
  BOTTOM w0.254: 45.3,30.82 U8.19
  BOTTOM w0.508: R147.1 46.97,30.44
  BOTTOM w0.635: 46.97,30.44 45.68,30.44 45.3,30.82
UNNAMED_25_P87524BRNFRQ1ES22P_3: length 4.2
  BOTTOM w0.254: U8.16 44.2,32.32 44.34,32.46 45.05,32.46 45.22,32.63
  BOTTOM w0.508: 45.22,32.63 46.37,32.63 R143.1
UNNAMED_25_P87524BRNFRQ1ES22P_4: length 2.8
  BOTTOM w0.102: U8.5 39.75,31.82 39.58,31.99 39.06,31.99 38.86,31.79 38.27,31.79 R146.2
UNNAMED_25_P87524BRNFRQ1ES22P_5: length 2.5
  BOTTOM w0.102: U8.6 39.75,32.32 39.64,32.22 38.93,32.22 38.76,32.05 R144.2
UNNAMED_25_P87524BRNFRQ1ES22PRE: length 14.8
  TOP w0.102: v1(48.74,34.56) 49.9,33.39 49.9,32.73 51.38,31.25 51.38,29.1 50.6,28.32 v1(49.96,28.32)
  BOTTOM w0.102: R148.1 50.23,28.6 v1(49.96,28.32) ; U8.15 44.65,32.82 44.89,33.06 45.99,33.06 47.52,34.58 48.71,34.58 v1(48.74,34.56)
UNNAMED_33_CAPNONPOLARIZED_I75_: length 2.8
  TOP w0.508: R78.1 30.34,33.37 C16.2 30.35,33.36 U3.3
UNNAMED_33_CAPNONPOLARIZED_I77_: length 3.8
  TOP w0.102: R87.2 30.88,23.74 C24.2 32.76,23.77 R85.1
UNNAMED_33_OSTTE030161_I26_1: length 37.6
  TOP w0.102: v1(31.29,19.16) 31.29,21.25 33.24,23.2 33.24,24.46 32.99,24.71 R85.2 32.44,24.71 31.62,25.53 U3.7
  BOTTOM w0.102: J3.1 17.76,1.97 23.67,1.97 29.76,8.06 29.76,14.92 30.55,15.71 30.55,18.49 31.22,19.16 v1(31.29,19.16)
UNNAMED_33_OSTTE030161_I26_3: length 28.8
  TOP w0.102: U3.6 30.35,25.53 29.52,24.7 R87.1 28.75,24.44 28.74,24.44 28.71,24.41 28.71,24.4 28.34,24.03 28.34,22.86 29.74,21.46 29.74,20.07 30.07,19.74 30.07,17.49 v1(29.74,17.16)
  BOTTOM w0.102: v1(29.74,17.16) 30.32,16.57 30.32,15.81 29.53,15.02 29.53,8.62 24.5,3.59 J3.3
UNNAMED_33_RESISTOR_I42_1: length 6.9
  TOP w0.102: R178.2 34.27,25.14 R86.1 ; R86.1 33.83,24.96 32.89,25.91 U3.8 ; R86.1 34.26,24.7 34.44,24.52 34.44,22.92 33.83,22.32 R177.1
UNNAMED_34_1050170001_I95_1: length 6.4
  BOTTOM w0.254: 53.31,4.15 J8.1
  BOTTOM w0.381: R161.1 53.31,8.24 53.31,4.15
UNNAMED_34_1050170001_I95_5: length 7.7
  BOTTOM w0.381: J8.5 50.72,4.15 50.72,5.25
  BOTTOM w0.508: 50.72,5.25 50.72,5.96 50.21,6.46 R175.2
UNNAMED_34_1050170001_I95_G1: length 26
  TOP w0.254: U10.5 52.8,12.66 53.24,12.23 53.24,11.87
  TOP w0.508: 53.24,11.87 53.24,11.13 49.51,7.41 J8.G2
  TOP w0.762: J8.G2 J8.G1
  BOTTOM w0.508: R174.2 58.8,4.15 J8.G1
  BOTTOM w0.762: J8.G1 55.51,3.15 J8.G3 ; J8.G4 48.51,3.15 J8.G2
UNNAMED_34_CAPNONPOLARIZED_I11_: length 10
  TOP w0.508: v1(4.21,27.15) 4.21,25.02 5.45,23.77 5.45,21.89 v1(5.78,21.56)
  BOTTOM w0.305: v1(5.78,21.56) 5.45,21.23 U9.5
  BOTTOM w0.508: R157.2 7.66,22.42 R156.1 6.62,22.4 v1(5.78,21.56) ; C78.1 4.31,27.07 4.24,27.15 v1(4.21,27.15)
UNNAMED_34_CAPNONPOLARIZED_I75_: length 5
  TOP w0.762: R176.1 2.51,23.83 1.8,24.54 v1(1.8,24.64)
  BOTTOM w0.305: 3.23,25.42 U9.1 U9.2
  BOTTOM w0.381: C79.2 3.23,25.42
  BOTTOM w0.508: 3.25,25.44 C80.2 1.8,25.02
  BOTTOM w0.635: v1(1.8,24.64) 1.8,25.02
UNNAMED_35_CAPNONPOLARIZED_I121: length 2.6
  BOTTOM w0.203: U6.68 24.74,40.83 R134.1
  BOTTOM w0.508: C49.2 24.85,41.75 R134.1
UNNAMED_35_CAPNONPOLARIZED_I122: length 9.3
  BOTTOM w0.102: U6.89 24.16,32.43 25.72,30.86 25.72,29.59 26.35,28.97 26.93,28.97 27.17,29.21 28.71,29.21 28.85,29.06 ; Y2.3 28.85,29.06 ; 28.85,29.06 C70.2
UNNAMED_35_CAPNONPOLARIZED_I123: length 5.6
  BOTTOM w0.102: U6.88 23.35,32.79 25.94,32.79 Y2.1 26.65,32.4 C63.2
UNNAMED_35_CAPNONPOLARIZED_I137: length 5.7
  TOP w0.508: v1(21.69,29.29) 22.01,29.29 22.51,29.79 C71.2 22.8,29.11 21.85,28.17 R154.1
  BOTTOM w0.203: U6.96 22.03,29.63 v1(21.69,29.29)
UNNAMED_35_CAPNONPOLARIZED_I139: length 6.4
  BOTTOM w0.203: U6.9 6.97,32.83
  BOTTOM w0.508: C66.2 6.34,32.83 6.97,32.83 ; C66.2 6.33,33.31 5.37,34.27 R140.1 5.27,34.6 4.89,34.98 U7.1 ; C66.2 6.33,31.78 C67.2
UNNAMED_35_RESISTOR_I24_2: length 1.6
  BOTTOM w0.102: U6.59 19.81,45.09 R125.2
UNNAMED_35_RESISTOR_I29_1: length 24.2
  TOP w0.102: v1(14.34,36.45) 14.34,31.7 19.1,26.94 19.1,26.12 19.5,25.72 v1(19.48,25.72)
  BOTTOM w0.102: v1(14.34,36.45) 16,38.1 20.11,38.1 22.04,40.03 23.31,40.03 U6.70 ; v1(19.48,25.72) 19.5,25.72 19.7,25.52 R155.1
UNNAMED_35_RESISTOR_I77_1: length 1.6
  BOTTOM w0.152: U6.62 21.01,44.93 R126.1
UNNAMED_35_RESISTOR_I78_1: length 17.5
  BOTTOM w0.203: U6.60 20.21,42.45
  BOTTOM w0.254: 20.21,42.45 20.59,42.06 22.14,42.06 22.47,42.39 23.29,42.39 23.59,42.7 23.59,46.69 22.88,47.4 22.88,47.98 22.32,48.54 19.12,48.54 18,47.42 18,46.26 R127.1
UNNAMED_35_RESISTOR_I79_1: length 13.9
  BOTTOM w0.102: R124.1 18.81,46.58 19.48,47.24 19.48,47.65 19.93,48.11 22.14,48.11 22.55,47.7 22.55,47.19 23.16,46.58 23.16,43.15 22.78,42.77 22.29,42.77 22.02,42.49 20.72,42.49 20.62,42.6 20.62,43.52 U6.61
UNNAMED_35_RESISTOR_I80_1: length 1.8
  BOTTOM w0.102: R123.1 21.41,44.67 U6.63
UNNAMED_35_RESISTOR_I83_1: length 2.8
  TOP w0.508: v1(22.02,30.53) 22.02,30.86 22.5,31.34 R152.1
  BOTTOM w0.203: v1(22.02,30.53) 22.52,30.03 U6.95
UNNAMED_35_RESISTOR_I124_2: length 1.7
  BOTTOM w0.102: U6.33 9.41,44.48 R128.2
UNNAMED_35_RESISTOR_I125_2: length 1.5
  BOTTOM w0.102: R129.2 9.81,44.92 U6.34
UNNAMED_35_RESISTOR_I138_2: length 2.5
  BOTTOM w0.102: R136.2 R135.2 6.73,39.19 7.87,39.19 U6.25
UNNAMED_37_RESISTOR_I1_1: length 1.1
  TOP w0.102: U11.3 42.9,29.66 R179.1
UNNAMED_37_RESISTOR_I2_2: length 1
  TOP w0.102: U11.1 42.91,30.66 R180.2
UNNAMED_37_RESISTOR_I6_2: length 1.1
  TOP w0.102: U11.4 45.93,29.66 R181.2
UNNAMED_37_RESISTOR_I7_1: length 1
  TOP w0.102: R182.1 45.4,30.76 U11.6
UNNAMED_37_RESISTOR_I8_1: length 2.1
  TOP w0.305: R183.1 46.27,30.16 U11.5
  TOP w0.508: C84.2 46.3,30.22 R183.1
UNNAMED_37_RESISTOR_I9_1: length 1.1
  TOP w0.102: U12.3 6.22,30.31 R184.1
UNNAMED_37_RESISTOR_I10_2: length 1
  TOP w0.102: U12.1 9.07,30.31 R185.2
UNNAMED_37_RESISTOR_I13_1: length 1
  TOP w0.102: R186.1 9.16,28.83 U12.6
UNNAMED_37_RESISTOR_I14_1: length 2.1
  TOP w0.254: U12.5 7.71,27.81 R187.1
  TOP w0.508: R187.1 8.75,27.81 C85.2
UNNAMED_37_RESISTOR_I15_1: length 1.2
  TOP w0.102: R188.1 7.21,28.3 U12.4
XDSET_1_DM: length 55.9
  TOP w0.132: U10.1 53.76,13.46 v1(53.92,13.61)
  BOTTOM w0.152: J8.2 52.66,9.49 53.74,10.57 53.74,13.44 v1(53.92,13.61) 53.89,13.64 52.65,13.64 46.84,19.44 32.76,19.44 31.9,20.31 28.11,20.31 27.06,19.25 25.6,19.25 24.86,19.99 24.86,28.12 25.32,28.57 25.32,30.24 24.8,30.76 23.38,30.76 U6.93
XDSET_1_DP: length 55.9
  TOP w0.132: v1(52.5,12.24) 52.3,12.44 U10.4
  BOTTOM w0.152: J8.3 52.01,4.98 52.38,5.35 52.38,9.61 53.46,10.68 53.46,12.53 53.23,12.76 53.02,12.76 v1(52.5,12.24) 52.5,13.4 46.73,19.16 32.65,19.16 31.78,20.03 28.23,20.03 27.17,18.97 25.48,18.97 24.58,19.87 24.58,28.23 25.04,28.69 25.04,30.12 24.68,30.48 23.36,30.48 U6.94
XDSET_1_ID: length 52.2
  TOP w0.102: v1(51.28,7.82) 54.79,11.33 54.79,14.14 v1(54.54,14.39) 53.63,14.39 52.8,13.56 U10.2
  TOP w0.254: v1(27.53,28.7) 26.59,28.7 25.14,30.15 25.14,30.66 24.45,31.34 R152.2
  L3 w0.254: v1(54.54,14.39) 53.71,14.39 48.43,19.67 40.66,19.67 34.13,26.2 29.94,26.2 27.53,28.61 v1(27.53,28.7)
  BOTTOM w0.102: v1(51.28,7.82) 51.36,7.74 J8.4
XDSET_1_VBUS: length 76
  TOP w0.381: U10.6 54.22,12.86 54.3,12.78 54.3,12.7 v1(54.35,12.7)
  TOP w0.508: v1(4.01,28.85) 4.97,28.85 5.43,28.4 5.43,27.55 5.04,27.16 5.04,25.72 5.51,25.26 10.26,25.26 11.72,26.72 17.1,26.72 19.42,24.4 19.42,22.42 20.24,21.6 21.58,21.6 22.17,22.19 22.17,26.34 R154.2 23.28,27.21 24.17,28.11 v1(25.7,28.11)
  L3 w0.381: v1(54.35,12.7) 54.29,12.64 53.36,12.64 51.61,14.39 51.61,15.63 48.2,19.04 40.35,19.04 33.72,25.67 29.81,25.67 27.55,27.93 25.88,27.93 v1(25.7,28.11)
  BOTTOM w0.508: R161.2 54.93,12.1 54.34,12.7 v1(54.35,12.7) ; v1(4.01,28.85) 5.06,28.85 R151.1
XDSET_TCK: length 23.5
  TOP w0.102: v1(28.29,42.44) 28.65,42.8 29.78,42.8 30.19,43.21 R70.2
  L3 w0.127: v1(9.77,42.37) 11.35,43.94 26.76,43.94 27.6,43.1 27.63,43.1 v1(28.29,42.44)
  BOTTOM w0.102: U6.35 10.21,42.8 v1(9.77,42.37)
XDSET_TDI: length 30.6
  TOP w0.102: v1(28.01,57.18) 28.01,57.2 27.9,57.31 R30.2
  L3 w0.127: v1(15.13,53.57) 15.13,54.58 16.94,56.39 19.82,56.39 20.26,56.83 20.26,57.06 20.82,57.62 22.48,57.62 22.65,57.45 24.79,57.45 25.66,56.59 27.42,56.59 v1(28.01,57.18)
  BOTTOM w0.102: v1(15.13,53.57) 15.13,52.65 13.71,51.23 11.7,51.23 10.1,49.63 10.1,48.77 10.94,47.93 10.94,45.39 11.2,45.14 11.2,44.73 11.41,44.52 U6.38
XDSET_TDO: length 23.4
  TOP w0.102: v1(29.28,42.37) 29.67,42.37 30.11,42.8 30.76,42.8 R71.2
  L3 w0.127: v1(29.28,42.37) 28.29,43.36 27.73,43.36 26.84,44.25 11.4,44.25 v1(10.71,44.93)
  BOTTOM w0.102: U6.37 11.01,44.58 10.71,44.88 v1(10.71,44.93)
XDSET_TMS: length 21.9
  TOP w0.102: v1(27.07,42.72) 27.56,43.21 R69.2
  L3 w0.127: v1(27.07,42.72) 26.1,41.76 23.03,41.76 21.18,43.61 12.06,43.61 v1(10.76,42.32)
  BOTTOM w0.102: U6.36 10.61,42.47 v1(10.76,42.32)

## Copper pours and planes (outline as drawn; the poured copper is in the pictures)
5V_IN on TOP: 41.29,8.52 43.31,8.52 43.33,8.53 43.33,11.3 42.74,11.89 41.73,11.89 41.12,12.5 41.12,19.22 39.82,19.22 39.82,9.99
5V_IN on TOP: 13.74,13.21 13,12.47 13,9.07 13.53,8.53 19.2,8.53 19.55,8.89 19.55,12.7 19.04,13.21
5V_IN on TOP: 40.68,55.37 40.91,55.14 42.14,55.14 43.68,56.68 43.68,60.07 41.24,60.07 40.68,59.51
5V_IN on L4: 43.05,10.03 43.05,8.56 42.79,8.31 36.47,8.31 35.05,9.73 30.5,9.73 29.38,8.61 13.48,8.61 13,9.09 13,11.38 14.12,12.5 20.19,12.5 28.29,20.6 28.29,42.34 34.64,48.69 34.64,49.92 34,50.56 34,54.8 39.38,60.17 42.82,60.17 43.4,59.59 43.4,52.55 35.43,44.58 35.43,15.7 37.38,15.7 ; 1 cut-out
5V_UNREG on TOP: 43.94,8.62 43.94,11.29 44.88,12.23 44.88,15.15 45.28,15.56 47.31,15.56 47.44,15.43 47.44,8.62
5V_UNREG on BOTTOM: 37.92,25.46 37.92,27.85 38.52,28.45 38.53,28.45 38.79,28.71 40.79,28.71 40.86,28.79 40.86,30.92 40.88,30.94 41.13,30.94 41.17,30.91 41.17,28.1 40.83,27.76 40.25,27.76 39.86,27.37 39.86,25.46
5V_UNREG on BOTTOM: 39.89,37.6 38.73,37.6 38.73,34.2 40.86,34.2 40.86,32.19 41.13,32.19 41.13,34.53 41.01,34.65 40.76,34.65 39.89,35.52
5V_UNREG on BOTTOM: 45.47,28.45 45.46,28.45 45.19,28.71 43.3,28.71 43.15,28.87 43.15,30.95 42.87,30.95 42.84,30.93 42.84,28.07 42.95,27.97 43.47,27.97 44.09,27.35 44.09,25.46 46.04,25.46 46.07,25.49 46.07,27.84
5V_UNREG on BOTTOM: 44.11,37.63 45.97,37.63 46.06,37.53 46.06,34.99 45.26,34.19 45.27,34.2 43.15,34.2 43.15,32.19 42.87,32.19 42.87,32.91 42.87,32.91 42.87,34.55 43.07,34.75 43.38,34.75 44.11,35.49
5V_UNREG on L4: 38.06,38.24 46.63,38.24 48.21,36.66 48.21,25.15 48.18,25.12 48.18,9.96 46.22,8 44.14,8 43.52,8.62 43.52,10.05 36.64,16.92 36.64,36.83 ; 1 cut-out
GND on TOP (solid shape): 71.05,6.52 63.46,6.52 63.46,14.19 71.05,14.19
GND on TOP (solid shape): 73.1,47.11 74.33,47.11 74.33,47.81 75.3,47.81 75.3,47.11 76.73,47.11 76.73,47.21 76.53,47.21 76.53,47.81 77.45,47.81 77.45,46.31 76.53,46.31 76.53,46.91 76.73,46.91 76.73,47.01 75.3,47.01 75.3,46.31 74.33,46.31 74.33,47.01 73.1,47.01 73.1,46.31 72.13,46.31 72.13,47.01 71,47.01 71,46.97 70,46.97 70,47.15 71,47.15 71,47.11 72.13,47.11 72.13,47.81 73.1,47.81
GND on TOP (solid shape): 73.1,37.61 74.33,37.61 74.33,38.31 75.3,38.31 75.3,37.61 76.73,37.61 76.73,37.71 76.53,37.71 76.53,38.31 77.45,38.31 77.45,36.81 76.53,36.81 76.53,37.41 76.73,37.41 76.73,37.51 75.3,37.51 75.3,36.81 74.33,36.81 74.33,37.51 73.1,37.51 73.1,36.81 72.13,36.81 72.13,37.51 71,37.51 71,37.47 70,37.47 70,37.65 71,37.65 71,37.61 72.13,37.61 72.13,38.31 73.1,38.31
GND on TOP (solid shape): 62.5,58.65 52.75,58.65 52.75,59.8 56.06,59.8 56.06,59.45 56.46,59.45 57.06,59.33 60.82,59.33 61.42,59.45 61.82,59.45 61.82,59.8 61.42,59.8 60.82,59.91 57.06,59.91 56.46,59.8 52.75,59.8 52.75,60.5 43.15,60.5 43.15,62.04 43.95,62.04 43.95,61.69 44.35,61.69 44.95,61.57 60.84,61.57 61.44,61.69 61.84,61.69 61.84,62.04 61.44,62.04 60.84,62.15 44.95,62.15 44.35,62.04 43.15,62.04 43.15,63.17 62.5,63.17
GND on BOTTOM (solid shape): 71.44,54.7 63.16,54.7 63.16,62.73 71.44,62.73
GND on BOTTOM (solid shape): 80,7.58 76.68,7.58 75.53,6.44 75.53,0.79 61.8,0.79 61.8,0.79 61.51,0.79 61.51,19.84 80,19.84
GND on L2 (solid shape): 70.35,55.37 64.13,55.37 64.13,61.65 70.35,61.65
GND on L2 (solid shape): 70.42,7.18 64.19,7.18 64.19,13.45 70.42,13.45
GND on L3 (solid shape): 70.35,55.37 66.33,55.37 64.13,57.57 64.13,61.65 70.35,61.65
GND on TOP: 59.76,0.76 59.76,15.9 57.93,17.73 57.93,23.06 57.75,23.24 56.69,23.24 56.66,23.27 56.66,24.71 58.05,24.71 60.47,27.14 60.47,28.24 60.17,28.55 60.17,29.57 59.99,29.74 59.99,36.8 60.01,36.83 60.01,37.87 58.86,39.03 58.86,40.46 58.68,40.64 58.68,44.44 59.67,45.43 59.68,45.43 61.04,46.79 67,46.79 69.39,49.18 70.71,49.18 70.71,31.47 72.61,31.47 72.61,29.41 70.71,29.41 70.71,15.46 72.92,13.26 80,13.26 80,5.76 75.7,4.13 80,2.49 80,1.73 79.04,0.76 ; 18 cut-outs
GND on TOP: 30.32,4.5 30.32,1.63 30.96,0.99 45.59,0.99 46.45,1.85 46.45,3.48 46.4,3.53 40.35,3.53 38.53,5.36 38.53,6.32 38.12,6.73 36.67,6.73 34.87,4.93 30.75,4.93
GND on TOP: 42.56,17.16 45.13,17.16 45.66,17.69 45.66,21.3 45.65,21.31 45.65,22.81 45.03,23.43 43.02,23.43 42.56,22.97
GND on TOP: 40.71,34.71 43.45,34.71 43.94,35.19 43.94,36.33 44.16,36.56 47.19,36.56 47.29,36.66 47.29,37.55 46.91,37.93 39.34,37.93 38.91,37.5 38.91,35.93 40.05,35.93 40.43,35.55 40.43,34.99
GND on TOP: 40.33,27.57 43.5,27.57 44.22,26.86 44.22,25.51 44.49,25.23 45.74,25.23 46.02,25.51 46.02,25.62 46.32,25.92 47.06,25.92 47.16,25.82 47.16,25.31 46.02,24.17 37.15,24.17 36.85,24.47 36.85,25.9 36.93,25.97 37.81,25.97 37.93,25.86 37.93,25.35 38.14,25.13 39.57,25.13 39.64,25.21 39.64,26.89
GND on TOP: 6.88,30.06 6.88,29.12 8.53,29.12 8.53,30.06
GND on TOP: 43.81,29.32 45.03,29.32 45.03,30.98 43.81,30.98
GND on BOTTOM: 68.35,38.25 65.83,38.25 64.61,39.47 64,39.47 63.62,39.47 63.6,39.5 63.6,39.7 64,40.11 65.14,40.11 65.35,39.9 68.35,39.9
GND on BOTTOM: 53.05,49.76 53.41,50.11 53.41,52.65 53,53.06 48.2,53.06 47.62,52.48 47.62,49.81 47.67,49.76
GND on BOTTOM: 34.66,52.32 34.66,51 34.97,50.7 39.16,50.7 39.44,50.98 39.44,52.27 38.86,52.86 35.2,52.86
GND on BOTTOM: 43.39,26.96 43.06,26.96 42.26,27.76 42.13,27.88 42.13,30.94 41.87,30.94 41.87,27.9 40.91,26.93 40.52,26.93 40.52,25.18 39.82,24.48 39.82,23.35 44.05,23.35 44.05,24.52 43.39,25.18
GND on BOTTOM: 58.29,0.83 58.29,7.8 50.84,7.8 50.83,7.81 47.87,7.81 42.59,13.09 42.59,18.66 42.77,18.83 49.89,18.83 51.78,20.73 51.78,34.39 50.39,35.79 50.39,43.74 47.85,43.74 47.56,44.03 47.56,44.41 47.44,44.53 47.44,45.26 47.69,45.52 52.95,45.52 53.49,46.05 62.45,46.05 63.67,47.27 68.19,47.27 68.37,47.09 68.37,46.46 67.56,45.64 67.56,43.38 67.41,43.23 65.37,43.23 65.35,43.26 65.35,45.06 65.09,45.31 64.13,45.31 63.57,44.75 63.57,44.09 63.6,44.07 63.6,37.52 64.46,36.65 66.08,36.65 66.41,36.32 67.84,36.32 68.12,36.6 71.8,36.6 74.16,38.96 74.16,51.52 74.59,51.96 74.59,53.4 73.79,54.2 63.48,54.2 62.96,54.72 62.96,63.79 63.39,64.22 78.99,64.22 79.86,63.35 79.86,62.81 75.7,60.92 80.01,59.39 80.01,5.76 75.7,4.23 79.87,2.35 79.87,1.53 79.17,0.83 ; 2 cut-outs
GND on BOTTOM: 39.85,39.27 39.85,38.12 40.55,37.42 40.55,35.69 40.85,35.69 41.79,34.75 41.79,32.19 42.2,32.19 42.2,34.75 43.2,35.76 43.48,35.76 43.48,37.24 44.12,37.88 44.12,39.27
GND on L2: 1.78,0.76 1.06,1.06 0.76,1.78 0.76,63.37 0.79,63.59 0.86,63.8 1.23,64.23 1.78,64.39 78.99,64.39 79.71,64.09 80.01,63.37 80.01,1.78 79.91,1.35 79.65,1 79.34,0.82 78.99,0.76 ; 15 cut-outs
GND on L3: 1.78,0.76 1.06,1.06 0.76,1.78 0.76,63.37 1.06,64.09 1.78,64.39 78.99,64.39 79.71,64.09 80.01,63.37 80.01,1.78 79.71,1.06 78.99,0.76 ; 40 cut-outs
GND on L4: 78.99,64.39 79.71,64.09 80.01,63.37 80.01,1.78 79.71,1.06 78.99,0.76 1.78,0.76 1.06,1.06 0.76,1.78 0.76,63.37 1.06,64.09 1.78,64.39 ; 8 cut-outs
GND on L5: 78.99,64.39 79.71,64.09 80.01,63.37 80.01,1.78 79.71,1.06 78.99,0.76 1.78,0.76 1.06,1.06 0.76,1.78 0.76,63.37 1.06,64.09 1.78,64.39
(no net) on L4: 50.06,45.92 44.47,45.92 44.47,40.3 44.79,39.98 51.66,39.98 52.46,40.78 55.56,40.78 56.36,39.98 58.34,39.98 58.59,40.23 58.59,40.59 58.29,40.89 57.88,40.89 57.52,41.25 57.52,44.55 57.83,44.86 58.44,44.86 58.79,44.5 58.79,44.25 59,44.04 59.46,44.04 59.76,44.35 59.76,45.11 60.29,45.64 61.77,45.64 63.57,47.45 63.57,50.85 63.27,51.16 62.27,51.16 61.04,49.92 61.04,48.8 59.74,47.5 57.7,47.5 55.85,49.35 53.49,49.35
AR_1P3_RF1 on BOTTOM: 47.62,46.15 47.34,45.87 47.34,43.31 46.71,43.31 46.71,45.06 46.27,45.5 46.27,47.5 46.22,47.55 47.64,47.55 47.86,47.33 53.95,47.33 54.83,48.21 61.69,48.21 62.91,49.43 69.84,49.43 70.58,48.69 70.58,41.61 69.97,41 67.96,41 66.95,42.01 64.05,42.01 63.7,41.66 63.7,41.05 63.47,40.82 63.14,40.82 63.01,40.94 63.01,42.37 63.27,42.62 63.6,42.62 64.36,43.38 64.36,43.94 64.97,43.94 64.97,43.1 65.04,43.03 67.74,43.03 68.19,43.48 68.19,44.96 68.5,45.26 68.5,47.22 68.29,47.42 63.49,47.42 62.24,46.16 60.79,46.16 60.78,46.15
AR_1P3_RF2 on TOP: 47.36,49.16 47.57,49.36 47.57,50.56 46.83,51.3 44.04,51.3 43.17,50.43 42.74,50.43 42.46,50.71 41.12,50.71 41.12,48.55 41.24,48.43 42.39,48.43 43.1,49.14 43.1,49.26 43.4,49.57 45.64,49.57 46.04,49.16
AR_1P3_RF2 on BOTTOM: 53.74,47.83 54.34,48.44 61.49,48.44 62.71,49.66 70.43,49.66 71.22,48.87 71.22,40.61 68.73,38.13 65.47,38.13 64.69,38.91 64.69,39.01 64.46,39.24 63.37,39.24 63.24,39.12 63.24,38.07 64.28,37.03 66.31,37.03 66.41,36.93 70.81,36.93 73.4,39.52 73.4,50.93 70.53,53.8 67.13,53.8 65.32,51.99 60.93,51.99 59.38,50.44 54.27,50.44 52.93,49.1 47.8,49.1 47.8,49.39 47.54,49.64 47.54,50.89 47.42,51.02 47.42,52.54 46.81,52.54 46.81,50.75 46.2,50.14 46.2,48.29 46.22,48.27 47.33,48.27 47.77,47.83
AR_1V8 on TOP: 55.26,29.64 55.26,32.03 56.2,32.03 56.83,32.65 57.87,32.65 58.08,32.44 58.08,30.3 58.19,30.2 58.19,27.91 56.89,27.91 56.53,28.27 54.88,28.27 54.78,28.37 54.78,29.17
AR_1V8 on BOTTOM: 64.18,41.35 64.18,40.46 64.84,40.46 64.92,40.54 66.8,40.54 66.8,41.78 64.61,41.78
AR_1V8 on BOTTOM: 52.9,42.44 52.9,35.69 54.55,34.04 54.55,30.02 56.11,28.47 57.12,28.47 57.25,28.35 58.77,28.35 58.77,30.7 58.25,31.21 57.56,31.21 56.08,32.69 56.08,36.21 58.24,38.37 58.24,38.84 58.9,38.84 59.05,38.99 59.05,43.23 58.67,43.61 56.08,43.61 55.82,43.36 53.82,43.36
AR_1V8 on L4: 54,36.73 53.49,36.22 53.49,30.65 53.74,30.39 53.74,29.25 54.6,28.38 61.56,28.38 66.54,33.36 66.54,37.12 66.57,37.12 67.68,38.24 67.68,39.18 66.54,40.32 66.54,44.32 66.36,44.5 63.16,44.5 63.06,44.4 63.06,40.73 63,40.67 63,39.87 63.35,39.51 63.7,39.51 63.75,39.46 64.59,39.46 64.97,39.08 64.97,38.8 64.61,38.44 63.32,38.44 63.3,38.46 62.5,38.46 60.88,36.83 56.47,36.83 56.38,36.73
AR_VOUT_PA on TOP: 64.62,37.95 64.56,37.88 64.56,36.91 64.56,36.09 64.43,35.96 64.43,33.76 64.79,33.4 67.15,33.4 67.28,33.53 67.28,34.65 67.13,34.8 65.25,34.8 65.09,34.95 65.09,37.91 65.06,37.95
AR_VOUT_PA on BOTTOM: 70,36.25 70,34.24 69.16,33.4 64.61,33.4 64.51,33.5 64.51,34.62 64.66,34.77 68.37,34.77 68.88,35.28 68.88,36.25
MCU_5V on TOP: 13.2,19.23 13.2,18.41 13.89,17.73 13.89,16.99 13.91,16.97 16.63,16.97 16.66,16.99 16.66,17.7 17.55,18.59 17.55,19.3 17.24,19.61 13.58,19.61
MCU_5V on BOTTOM: 47.47,16.21 47.47,13.39 47.9,12.95 50.41,12.95 50.64,13.18 50.64,16.31 50.41,16.54 47.8,16.54
MCU_5V on BOTTOM: 13.15,19.16 13.15,16.7 13.94,15.91 17.37,15.91 17.44,15.99 17.44,16.83 16.83,17.44 16.83,17.95 17.27,18.38 17.27,19.14 17.11,19.29 13.28,19.29
MCU_5V on L3: 19.04,10.31 47.95,10.31 49.93,12.29 49.93,15.32 48.86,16.38 47.82,16.38 47.52,16.08 47.52,12.88 47.09,12.45 46.32,12.45 45.57,13.2 43.11,13.2 42.59,13.72 26.74,13.72 25.65,12.62 22.32,12.62 17.67,17.27 17.67,18.95 17.34,19.28 13.18,19.28 12.9,19 12.9,16.46
Net_37 on TOP (solid shape): 59.09,61.77 44.95,61.77 44.95,61.95 59.09,61.95
PMIC_1V2 on L4 (solid shape): outline of 409 points within 44.47,39.98 63.57,51.16
PMIC_1V2 on BOTTOM: 42.24,41.12 42.24,42.96 45.19,42.96 45.2,42.97 47.61,42.97 48.05,43.41 49.55,43.41 49.55,40.39 48.86,39.7 46.65,39.7 46.63,39.68 44.64,39.68 44.63,39.69 44.63,40.56 44.06,41.12
PMIC_1V8 on TOP: 38.32,50.1 38.32,47.41 39.41,46.32 39.74,46.32 39.95,46.52 39.95,46.82 40.51,46.82 40.66,46.98 40.66,48.43 40.07,49.01 40.07,50.84 39.95,50.97 39.19,50.97
PMIC_1V8 on BOTTOM: 39.03,48.84 39.59,49.4 42.79,49.4 43.07,49.12 43.07,48.26 42.18,48.26 42.03,48.41 41.32,48.41 41.14,48.23 41.14,47.73 41.4,47.47 42.08,47.47 42.18,47.57 43.07,47.57 43.07,46.3 42.72,45.95 37.2,45.95 36.54,45.29 36.54,24.57 37.21,23.91 37.22,23.92 39.22,23.92 39.23,23.91 39.23,22.12 39.85,21.5 41.62,21.5 41.62,20.36 37.52,20.36 35.12,22.76 35.12,23.29 34.39,24.03 34.39,48.56 34.66,48.84
PMIC_2V3 on TOP: 54.76,26.11 54.89,26.24 55.85,26.24 55.85,26.23 56.25,26.63 56.46,26.63 56.76,26.94 56.71,26.99 56.71,27.57 56.79,27.65 58.36,27.65 58.67,27.34 58.67,26.1 58.64,26.07 57.65,26.07 57.54,25.96 57.54,25.11 56.23,25.11 56.03,24.9 56.03,20.9 55.23,20.1 46.86,20.1 46.86,23.44 54.43,23.44 54.76,23.77
PMIC_2V3 on BOTTOM: 42.23,21.5 42.23,20.09 49.28,20.09 49.73,20.54 49.73,22.26 49.12,22.87 46.64,22.87 46.63,22.89 44.63,22.89 44.62,22.87 44.62,22.07 44.05,21.5
PMIC_2V3 on BOTTOM: 56.38,27.47 56.38,25.67 58.97,25.67 58.97,27.47
PMICOUT_3V3 on BOTTOM: 41.73,41.12 41.73,42.95 41.01,42.95 40.49,43.47 38.47,43.47 38.47,43.08 38.47,43.07 38.47,42.55 37.36,41.45 37.36,39.69 37.38,39.68 39.37,39.68 39.38,39.69 39.38,40.58 39.92,41.12
RX1 on TOP (solid shape): 73.1,45.21 74.33,45.21 74.33,45.91 75.3,45.91 75.3,45.21 76.73,45.21 76.73,45.31 76.53,45.31 76.53,45.91 77.45,45.91 77.45,44.41 76.53,44.41 76.53,45.01 76.73,45.01 76.73,45.11 75.3,45.11 75.3,44.41 74.33,44.41 74.33,45.11 73.1,45.11 73.1,44.41 72.13,44.41 72.13,45.11 71,45.11 71,45.07 70,45.07 70,45.25 71,45.25 71,45.21 72.13,45.21 72.13,45.91 73.1,45.91
RX2 on TOP (solid shape): 73.1,43.31 74.33,43.31 74.33,44.01 75.3,44.01 75.3,43.31 76.73,43.31 76.73,43.41 76.53,43.41 76.53,44.01 77.45,44.01 77.45,42.51 76.53,42.51 76.53,43.11 76.73,43.11 76.73,43.21 75.3,43.21 75.3,42.51 74.33,42.51 74.33,43.21 73.1,43.21 73.1,42.51 72.13,42.51 72.13,43.21 71,43.21 71,43.17 70,43.17 70,43.35 71,43.35 71,43.31 72.13,43.31 72.13,44.01 73.1,44.01
RX3 on TOP (solid shape): 73.1,41.41 74.33,41.41 74.33,42.11 75.3,42.11 75.3,41.41 76.73,41.41 76.73,41.51 76.53,41.51 76.53,42.11 77.45,42.11 77.45,40.61 76.53,40.61 76.53,41.21 76.73,41.21 76.73,41.31 75.3,41.31 75.3,40.61 74.33,40.61 74.33,41.31 73.1,41.31 73.1,40.61 72.13,40.61 72.13,41.31 71,41.31 71,41.27 70,41.27 70,41.45 71,41.45 71,41.41 72.13,41.41 72.13,42.11 73.1,42.11
RX4 on TOP (solid shape): 73.1,39.51 74.33,39.51 74.33,40.21 75.3,40.21 75.3,39.51 76.73,39.51 76.73,39.61 76.53,39.61 76.53,40.21 77.45,40.21 77.45,38.71 76.53,38.71 76.53,39.31 76.73,39.31 76.73,39.41 75.3,39.41 75.3,38.71 74.33,38.71 74.33,39.41 73.1,39.41 73.1,38.71 72.13,38.71 72.13,39.41 71,39.41 71,39.37 70,39.37 70,39.55 71,39.55 71,39.51 72.13,39.51 72.13,40.21 73.1,40.21
TX1 on TOP (solid shape): 73.1,34.27 74.33,34.27 74.33,34.97 75.3,34.97 75.3,34.27 76.73,34.27 76.73,34.37 76.53,34.37 76.53,34.97 77.45,34.97 77.45,33.47 76.53,33.47 76.53,34.07 76.73,34.07 76.73,34.17 75.3,34.17 75.3,33.47 74.33,33.47 74.33,34.17 73.1,34.17 73.1,33.47 72.13,33.47 72.13,34.17 71,34.17 71,34.13 70,34.13 70,34.31 71,34.31 71,34.27 72.13,34.27 72.13,34.97 73.1,34.97
TX2 on TOP (solid shape): 75,30.47 76.23,30.47 76.23,31.17 77.2,31.17 77.2,30.47 78.63,30.47 78.63,30.57 78.43,30.57 78.43,31.17 79.35,31.17 79.35,29.67 78.43,29.67 78.43,30.27 78.63,30.27 78.63,30.37 77.2,30.37 77.2,29.67 76.23,29.67 76.23,30.37 75,30.37 75,29.67 74.03,29.67 74.03,30.37 72.9,30.37 72.9,30.33 71.9,30.33 71.9,30.51 72.9,30.51 72.9,30.47 74.03,30.47 74.03,31.17 75,31.17
TX3 on TOP (solid shape): 73.1,26.67 74.33,26.67 74.33,27.37 75.3,27.37 75.3,26.67 76.73,26.67 76.73,26.77 76.53,26.77 76.53,27.37 77.45,27.37 77.45,25.87 76.53,25.87 76.53,26.47 76.73,26.47 76.73,26.57 75.3,26.57 75.3,25.87 74.33,25.87 74.33,26.57 73.1,26.57 73.1,25.87 72.13,25.87 72.13,26.57 71,26.57 71,26.53 70,26.53 70,26.71 71,26.71 71,26.67 72.13,26.67 72.13,27.37 73.1,27.37
UNNAMED_6_QSH03001XD_I1_1 on TOP: 29.89,56.06 29.89,53.64 30.07,53.47 32.66,53.47 33.04,53.09 33.04,51.64 32.73,51.33 30.93,51.33 30.4,50.8 30.4,48.03 32.07,48.03 32.07,49.91 32.81,50.65 34.59,50.65 34.89,50.95 34.89,54.23 36.04,55.37 36.93,55.37 36.95,55.4 36.95,58.14 36.77,58.32 35.68,58.32 35.5,58.14 35.5,57.23 34.33,56.06
